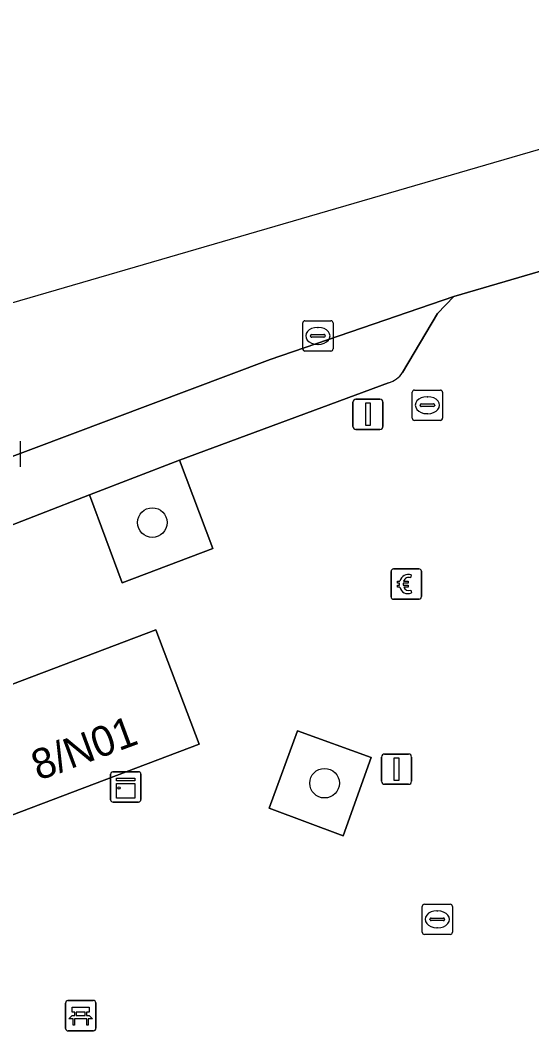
# Model space of a CAD drawing. Extents: x 159716 to 160783, y 383290 to 384031.
# Drawn here: x 159751.09 to 159767.98, y 383590.94 to 383624.33 of the extents above; entities that cross this region are included whole.
import ezdxf

# ---------------------------------------------------------------- set-up
doc = ezdxf.new("R2010")
doc.units = 0
for name, color, linetype in [('IMGEO_Bank', 7, 'Continuous'), ('IMGEO_Betaalautomaat', 7, 'Continuous'), ('IMGEO_Boom', 7, 'Continuous'), ('IMGEO_Groenvoorziening', 7, 'Continuous'), ('IMGEO_Kast', 7, 'Continuous'), ('IMGEO_Kolk', 7, 'Continuous'), ('IMGEO_Lichtmast', 7, 'Continuous'), ('IMGEO_Pand', 7, 'Continuous'), ('IMGEO_Pand_nummerreeks', 7, 'Continuous'), ('IMGEO_Parkeervlak_open', 7, 'Continuous'), ('IMGEO_Rijbaan_lokaal_open', 7, 'Continuous'), ('IMGEO_Rioolput', 7, 'Continuous'), ('IMGEO_Voetpad_open', 7, 'Continuous')]:
    doc.layers.add(name, color=color, linetype=linetype)

msp = doc.modelspace()

# ---------------------------------------------------------------- linework, layer by layer
at = {"layer": 'IMGEO_Bank'}
for p, q in [((159752.665, 383591.936), (159753.506, 383591.936)), ((159753.506, 383591.936), (159752.665, 383591.936)), ((159752.59, 383591.011), (159752.59, 383591.852)), ((159752.59, 383591.852), (159752.59, 383591.011)), ((159753.59, 383591.861), (159753.59, 383591.02)), ((159753.59, 383591.02), (159753.59, 383591.861)), ((159753.287, 383591.334), (159752.894, 383591.334)), ((159752.899, 383591.442), (159752.899, 383591.548)), ((159752.943, 383591.548), (159752.943, 383591.442)), ((159753.231, 383591.554), (159752.949, 383591.554)), ((159752.949, 383591.436), (159753.231, 383591.436)), ((159753.237, 383591.442), (159753.237, 383591.548)), ((159753.281, 383591.548), (159753.281, 383591.442)), ((159753.515, 383590.936), (159752.674, 383590.936)), ((159752.674, 383590.936), (159753.515, 383590.936))]:
    msp.add_line(p, q, dxfattribs=at)
for points in [[(159752.893, 383591.554), (159752.807, 383591.554), (159752.807, 383591.715), (159753.37, 383591.715), (159753.37, 383591.554), (159753.287, 383591.554)], [(159752.837, 383591.334), (159752.695, 383591.334), (159752.807, 383591.436), (159752.893, 383591.436)], [(159752.887, 383591.327), (159752.887, 383591.12), (159752.844, 383591.12), (159752.844, 383591.327)], [(159753.287, 383591.436), (159753.37, 383591.436), (159753.482, 383591.334), (159753.343, 383591.334)], [(159753.337, 383591.327), (159753.337, 383591.12), (159753.293, 383591.12), (159753.293, 383591.327)]]:
    msp.add_lwpolyline(points, dxfattribs=at)
for centre, radius, start, end in [((159752.668, 383591.858), 0.0779, 92.4484, 184.2845), ((159752.668, 383591.858), 0.0779, 92.4484, 184.2845), ((159753.512, 383591.858), 0.0779, 2.4484, 94.2845), ((159753.512, 383591.858), 0.0779, 2.4484, 94.2845), ((159752.837, 383591.327), 0.00671, 2.8957, 87.1043), ((159752.894, 383591.327), 0.00671, 92.8957, 177.1043), ((159752.892, 383591.547), 0.00671, 2.8957, 87.1043), ((159752.892, 383591.443), 0.00671, 272.8957, 357.1043), ((159752.949, 383591.547), 0.00671, 92.8957, 177.1043), ((159752.949, 383591.443), 0.00671, 182.8957, 267.1043), ((159753.231, 383591.547), 0.00671, 2.8957, 87.1043), ((159753.231, 383591.443), 0.00671, 272.8957, 357.1043), ((159753.288, 383591.547), 0.00671, 92.8957, 177.1043), ((159753.288, 383591.443), 0.00671, 182.8957, 267.1043), ((159753.286, 383591.327), 0.00671, 2.8957, 87.1043), ((159753.343, 383591.327), 0.00671, 92.8957, 177.1043), ((159752.668, 383591.014), 0.0779, 182.4484, 274.2845), ((159752.668, 383591.014), 0.0779, 182.4484, 274.2845), ((159753.512, 383591.014), 0.0779, 272.4484, 4.2845), ((159753.512, 383591.014), 0.0779, 272.4484, 4.2845)]:
    msp.add_arc(centre, radius, start, end, dxfattribs=at)
at = {"layer": 'IMGEO_Betaalautomaat'}
for p, q in [((159763.336, 383605.274), (159763.336, 383606.115)), ((159763.336, 383606.115), (159763.336, 383605.274)), ((159763.411, 383606.198), (159764.252, 383606.198)), ((159764.252, 383606.198), (159763.411, 383606.198)), ((159763.998, 383606.003), (159763.981, 383605.903)), ((159764.335, 383606.124), (159764.335, 383605.283)), ((159764.335, 383605.283), (159764.335, 383606.124)), ((159763.619, 383605.662), (159763.619, 383605.73)), ((159763.74, 383605.73), (159763.74, 383605.662)), ((159763.985, 383605.497), (159764.007, 383605.41)), ((159764.261, 383605.199), (159763.42, 383605.199)), ((159763.42, 383605.199), (159764.261, 383605.199))]:
    msp.add_line(p, q, dxfattribs=at)
for points in [[(159763.619, 383605.73), (159763.55, 383605.73), (159763.55, 383605.799), (159763.629, 383605.799)], [(159763.624, 383605.593), (159763.55, 383605.593), (159763.55, 383605.662), (159763.619, 383605.662)], [(159763.751, 383605.799), (159763.898, 383605.799), (159763.898, 383605.73), (159763.74, 383605.73)], [(159763.74, 383605.662), (159763.898, 383605.662), (159763.898, 383605.593), (159763.754, 383605.593)]]:
    msp.add_lwpolyline(points, dxfattribs=at)
for centre, radius, start, end in [((159763.414, 383606.121), 0.0779, 92.4484, 184.2845), ((159763.414, 383606.121), 0.0779, 92.4484, 184.2845), ((159763.912, 383605.723), 0.293, 73.014, 165.0139), ((159764.258, 383606.121), 0.0779, 2.4484, 94.2845), ((159764.258, 383606.121), 0.0779, 2.4484, 94.2845), ((159763.918, 383605.736), 0.179, 69.3236, 159.5683), ((159763.885, 383605.648), 0.267, 191.8096, 297.0389), ((159763.918, 383605.663), 0.179, 202.7625, 291.8693), ((159764.258, 383605.277), 0.0779, 272.4484, 4.2845), ((159764.258, 383605.277), 0.0779, 272.4484, 4.2845), ((159763.414, 383605.277), 0.0779, 182.4484, 274.2845), ((159763.414, 383605.277), 0.0779, 182.4484, 274.2845)]:
    msp.add_arc(centre, radius, start, end, dxfattribs=at)
at = {"layer": 'IMGEO_Boom'}
for centre in [(159755.455, 383607.729), (159761.139, 383599.118)]:
    msp.add_circle(centre, 0.489, dxfattribs=at)
at = {"layer": 'IMGEO_Groenvoorziening'}
for points in [[(159753.379, 383608.651), (159754.454, 383605.743), (159757.447, 383606.868), (159756.356, 383609.787)], [(159761.759, 383597.383), (159762.674, 383599.962), (159760.244, 383600.849), (159759.31, 383598.293)]]:
    msp.add_lwpolyline(points, close=True, dxfattribs=at)
at = {"layer": 'IMGEO_Kast'}
for p, q in [((159754.078, 383598.57), (159754.078, 383599.411)), ((159754.078, 383599.411), (159754.078, 383598.57)), ((159754.153, 383599.495), (159754.994, 383599.495)), ((159754.994, 383599.495), (159754.153, 383599.495)), ((159755.078, 383599.42), (159755.078, 383598.579)), ((159755.078, 383598.579), (159755.078, 383599.42)), ((159755.003, 383598.495), (159754.162, 383598.495)), ((159754.162, 383598.495), (159755.003, 383598.495))]:
    msp.add_line(p, q, dxfattribs=at)
for points in [[(159754.273, 383599.285), (159754.873, 383599.285), (159754.873, 383599.2), (159754.273, 383599.2), (159754.273, 383599.285)], [(159754.273, 383599.11), (159754.873, 383599.11), (159754.873, 383598.621), (159754.273, 383598.621), (159754.273, 383599.11)]]:
    msp.add_lwpolyline(points, dxfattribs=at)
msp.add_circle((159754.357, 383598.959), 0.0377, dxfattribs=at)
for centre, start, end in [((159754.156, 383599.417), 92.4484, 184.2845), ((159754.156, 383599.417), 92.4484, 184.2845), ((159755, 383599.417), 2.4484, 94.2845), ((159755, 383599.417), 2.4484, 94.2845), ((159754.156, 383598.573), 182.4484, 274.2845), ((159754.156, 383598.573), 182.4484, 274.2845), ((159755, 383598.573), 272.4484, 4.2845), ((159755, 383598.573), 272.4484, 4.2845)]:
    msp.add_arc(centre, 0.0779, start, end, dxfattribs=at)
at = {"layer": 'IMGEO_Kolk'}
for p, q in [((159760.419, 383613.473), (159760.419, 383614.325)), ((159760.494, 383614.399), (159761.346, 383614.399)), ((159761.42, 383614.325), (159761.42, 383613.473)), ((159760.907, 383614.179), (159760.932, 383614.179)), ((159760.678, 383613.893), (159760.678, 383613.905)), ((159761.116, 383613.856), (159760.718, 383613.856)), ((159760.721, 383613.942), (159761.119, 383613.942)), ((159761.162, 383613.905), (159761.162, 383613.893)), ((159761.346, 383613.399), (159760.494, 383613.399)), ((159760.93, 383613.619), (159760.905, 383613.619)), ((159751.094, 383610.419), (159751.094, 383609.567))]:
    msp.add_line(p, q, dxfattribs=at)
for points in [[(159760.419, 383613.473), (159760.419, 383614.325)], [(159760.494, 383614.399), (159761.346, 383614.399)], [(159761.42, 383614.325), (159761.42, 383613.473)], [(159761.346, 383613.399), (159760.494, 383613.399)], [(159751.094, 383610.419), (159751.094, 383609.567)]]:
    msp.add_lwpolyline(points, dxfattribs=at)
for centre, radius, start, end in [((159760.496, 383614.323), 0.0765, 91.552, 178.448), ((159760.496, 383614.323), 0.0765, 91.552, 178.448), ((159761.344, 383614.323), 0.0765, 1.552, 88.448), ((159761.344, 383614.323), 0.0765, 1.552, 88.448), ((159760.718, 383613.902), 0.0403, 85.8775, 175.7526), ((159760.715, 383613.892), 0.0366, 178.938, 274.7102), ((159761.119, 383613.899), 0.043, 264.8664, 352.4533), ((159761.123, 383613.904), 0.0386, 1.7309, 96.639), ((159760.496, 383613.475), 0.0765, 181.552, 268.448), ((159760.496, 383613.475), 0.0765, 181.552, 268.448), ((159761.344, 383613.475), 0.0765, 271.552, 358.448), ((159761.344, 383613.475), 0.0765, 271.552, 358.448)]:
    msp.add_arc(centre, radius, start, end, dxfattribs=at)
for centre, major_axis, ratio, start_param, end_param in [((159760.906, 383613.899), (-0.387, 0.002), 0.722429, 4.712389, 7.853982), ((159760.931, 383613.899), (-0.39, 0.002), 0.717154, 1.570796, 4.712389)]:
    msp.add_ellipse(centre, major_axis=major_axis, ratio=ratio, start_param=start_param, end_param=end_param, dxfattribs=at)
at = {"layer": 'IMGEO_Lichtmast'}
for p, q in [((159762.077, 383610.907), (159762.077, 383611.707)), ((159762.077, 383611.707), (159762.077, 383610.907)), ((159762.177, 383611.807), (159762.967, 383611.807)), ((159762.967, 383611.807), (159762.177, 383611.807)), ((159763.067, 383611.707), (159763.067, 383610.907)), ((159763.067, 383610.907), (159763.067, 383611.707)), ((159762.967, 383610.807), (159762.177, 383610.807)), ((159762.177, 383610.807), (159762.967, 383610.807)), ((159763.022, 383599.181), (159763.022, 383599.981)), ((159763.022, 383599.981), (159763.022, 383599.181)), ((159763.122, 383600.081), (159763.912, 383600.081)), ((159763.912, 383600.081), (159763.122, 383600.081)), ((159764.012, 383599.981), (159764.012, 383599.181)), ((159764.012, 383599.181), (159764.012, 383599.981)), ((159763.912, 383599.081), (159763.122, 383599.081)), ((159763.122, 383599.081), (159763.912, 383599.081))]:
    msp.add_line(p, q, dxfattribs=at)
for points in [[(159762.497, 383611.682), (159762.647, 383611.682), (159762.647, 383610.932), (159762.497, 383610.932), (159762.497, 383611.682)], [(159763.442, 383599.956), (159763.592, 383599.956), (159763.592, 383599.206), (159763.442, 383599.206), (159763.442, 383599.956)]]:
    msp.add_lwpolyline(points, dxfattribs=at)
for centre, start, end in [((159762.177, 383611.707), 90, 180), ((159762.177, 383611.707), 90, 180), ((159762.967, 383611.707), 0, 90), ((159762.967, 383611.707), 360, 90), ((159762.177, 383610.907), 180, 270), ((159762.177, 383610.907), 180, 270), ((159762.967, 383610.907), 270, 0), ((159762.967, 383610.907), 270, 0), ((159763.122, 383599.981), 90, 180), ((159763.122, 383599.981), 90, 180), ((159763.912, 383599.981), 0, 90), ((159763.912, 383599.981), 360, 90), ((159763.122, 383599.181), 180, 270), ((159763.122, 383599.181), 180, 270), ((159763.912, 383599.181), 270, 0), ((159763.912, 383599.181), 270, 0)]:
    msp.add_arc(centre, 0.1, start, end, dxfattribs=at)
at = {"layer": 'IMGEO_Pand'}
msp.add_lwpolyline([(159747.313, 383596.739), (159747.989, 383596.995), (159757, 383600.409), (159755.569, 383604.187), (159744.731, 383600.081), (159746.163, 383596.303)], close=True, dxfattribs=at)
at = {"layer": 'IMGEO_Parkeervlak_open'}
for points in [[(159763.716, 383612.687), (159764.868, 383614.637), (159765.409, 383615.2), (159759.342, 383613.121), (159748.858, 383609.172)], [(159741.056, 383603.334), (159743.799, 383604.621), (159746.603, 383605.923), (159748.457, 383606.733), (159753.379, 383608.651), (159756.356, 383609.787), (159763.252, 383612.344)]]:
    msp.add_lwpolyline(points, dxfattribs=at)
msp.add_arc((159763.008, 383613.159), 0.851, 286.6541, 326.2913, dxfattribs=at)
at = {"layer": 'IMGEO_Rijbaan_lokaal_open'}
for points in [[(159782.892, 383624.33), (159772.537, 383621.313), (159750.809, 383614.982), (159716.438, 383597.163), (159715.609, 383596.852), (159717.847, 383594.663), (159723.658, 383597.483), (159723.874, 383597.558), (159725.752, 383598.487), (159736.598, 383603.803), (159737.288, 383604.053), (159744.473, 383607.263)], [(159748.858, 383609.172), (159759.342, 383613.121), (159765.409, 383615.2), (159773.464, 383617.553), (159775.395, 383618.065), (159781.674, 383619.726), (159783.978, 383620.4), (159783.577, 383621.851), (159782.892, 383624.329), (159782.892, 383624.33)]]:
    msp.add_lwpolyline(points, dxfattribs=at)
at = {"layer": 'IMGEO_Rioolput'}
for p, q in [((159764.035, 383611.182), (159764.035, 383612.034)), ((159764.11, 383612.108), (159764.962, 383612.108)), ((159765.036, 383612.034), (159765.036, 383611.182)), ((159764.337, 383611.651), (159764.735, 383611.651)), ((159764.523, 383611.888), (159764.548, 383611.888)), ((159764.294, 383611.602), (159764.294, 383611.614)), ((159764.732, 383611.565), (159764.334, 383611.565)), ((159764.546, 383611.328), (159764.521, 383611.328)), ((159764.778, 383611.614), (159764.778, 383611.602)), ((159764.962, 383611.108), (159764.11, 383611.108)), ((159764.361, 383594.193), (159764.361, 383595.045)), ((159764.436, 383595.119), (159765.288, 383595.119)), ((159765.362, 383595.045), (159765.362, 383594.193)), ((159764.62, 383594.613), (159764.62, 383594.625)), ((159764.663, 383594.662), (159765.061, 383594.662)), ((159764.849, 383594.899), (159764.874, 383594.899)), ((159765.104, 383594.625), (159765.104, 383594.613)), ((159765.058, 383594.576), (159764.66, 383594.576)), ((159764.872, 383594.339), (159764.847, 383594.339)), ((159765.288, 383594.119), (159764.436, 383594.119))]:
    msp.add_line(p, q, dxfattribs=at)
for points in [[(159764.035, 383611.182), (159764.035, 383612.034)], [(159764.11, 383612.108), (159764.962, 383612.108)], [(159765.036, 383612.034), (159765.036, 383611.182)], [(159764.962, 383611.108), (159764.11, 383611.108)], [(159764.361, 383594.193), (159764.361, 383595.045)], [(159764.436, 383595.119), (159765.288, 383595.119)], [(159765.362, 383595.045), (159765.362, 383594.193)], [(159765.288, 383594.119), (159764.436, 383594.119)]]:
    msp.add_lwpolyline(points, dxfattribs=at)
for centre, radius, start, end in [((159764.112, 383612.032), 0.0765, 91.552, 178.448), ((159764.112, 383612.032), 0.0765, 91.552, 178.448), ((159764.96, 383612.032), 0.0765, 1.552, 88.448), ((159764.96, 383612.032), 0.0765, 1.552, 88.448), ((159764.334, 383611.611), 0.0403, 85.8775, 175.7526), ((159764.739, 383611.613), 0.0386, 1.7309, 96.639), ((159764.331, 383611.601), 0.0366, 178.938, 274.7102), ((159764.735, 383611.608), 0.043, 264.8664, 352.4533), ((159764.112, 383611.184), 0.0765, 181.552, 268.448), ((159764.112, 383611.184), 0.0765, 181.552, 268.448), ((159764.96, 383611.184), 0.0765, 271.552, 358.448), ((159764.96, 383611.184), 0.0765, 271.552, 358.448), ((159764.438, 383595.043), 0.0765, 91.552, 178.448), ((159764.438, 383595.043), 0.0765, 91.552, 178.448), ((159765.286, 383595.043), 0.0765, 1.552, 88.448), ((159765.286, 383595.043), 0.0765, 1.552, 88.448), ((159764.66, 383594.622), 0.0403, 85.8775, 175.7526), ((159764.657, 383594.612), 0.0366, 178.938, 274.7102), ((159765.061, 383594.619), 0.043, 264.8664, 352.4533), ((159765.065, 383594.624), 0.0386, 1.7309, 96.639), ((159764.438, 383594.195), 0.0765, 181.552, 268.448), ((159764.438, 383594.195), 0.0765, 181.552, 268.448), ((159765.286, 383594.195), 0.0765, 271.552, 358.448), ((159765.286, 383594.195), 0.0765, 271.552, 358.448)]:
    msp.add_arc(centre, radius, start, end, dxfattribs=at)
for centre, major_axis, ratio, start_param, end_param in [((159764.522, 383611.608), (-0.387, 0.002), 0.722429, 4.712389, 7.853982), ((159764.547, 383611.608), (-0.39, 0.002), 0.717154, 1.570796, 4.712389), ((159764.848, 383594.619), (-0.387, 0.002), 0.722429, 4.712389, 7.853982), ((159764.873, 383594.619), (-0.39, 0.002), 0.717154, 1.570796, 4.712389)]:
    msp.add_ellipse(centre, major_axis=major_axis, ratio=ratio, start_param=start_param, end_param=end_param, dxfattribs=at)
at = {"layer": 'IMGEO_Voetpad_open'}
for points in [[(159781.674, 383619.726), (159775.395, 383618.065), (159773.464, 383617.553), (159765.409, 383615.2), (159764.868, 383614.637), (159763.716, 383612.687)], [(159763.252, 383612.344), (159756.356, 383609.787), (159757.447, 383606.868), (159754.454, 383605.743), (159753.379, 383608.651), (159748.457, 383606.733), (159746.603, 383605.923), (159747.818, 383603.291), (159744.968, 383602.044), (159743.799, 383604.621), (159741.056, 383603.334)]]:
    msp.add_lwpolyline(points, dxfattribs=at)
for points in [[(159757, 383600.409), (159747.989, 383596.995), (159747.313, 383596.739), (159746.163, 383596.303), (159744.731, 383600.081), (159755.569, 383604.187)], [(159761.759, 383597.383), (159759.31, 383598.293), (159760.244, 383600.849), (159762.674, 383599.962)]]:
    msp.add_lwpolyline(points, close=True, dxfattribs=at)
msp.add_arc((159763.008, 383613.159), 0.851, 286.6541, 326.2913, dxfattribs=at)

# ---------------------------------------------------------------- texts
at = {"layer": 'IMGEO_Pand_nummerreeks'}
msp.add_text('8/N01', height=1, rotation=20.3142, dxfattribs=at).set_placement((159751.699, 383599.194))

doc.saveas('drawing.dxf')
